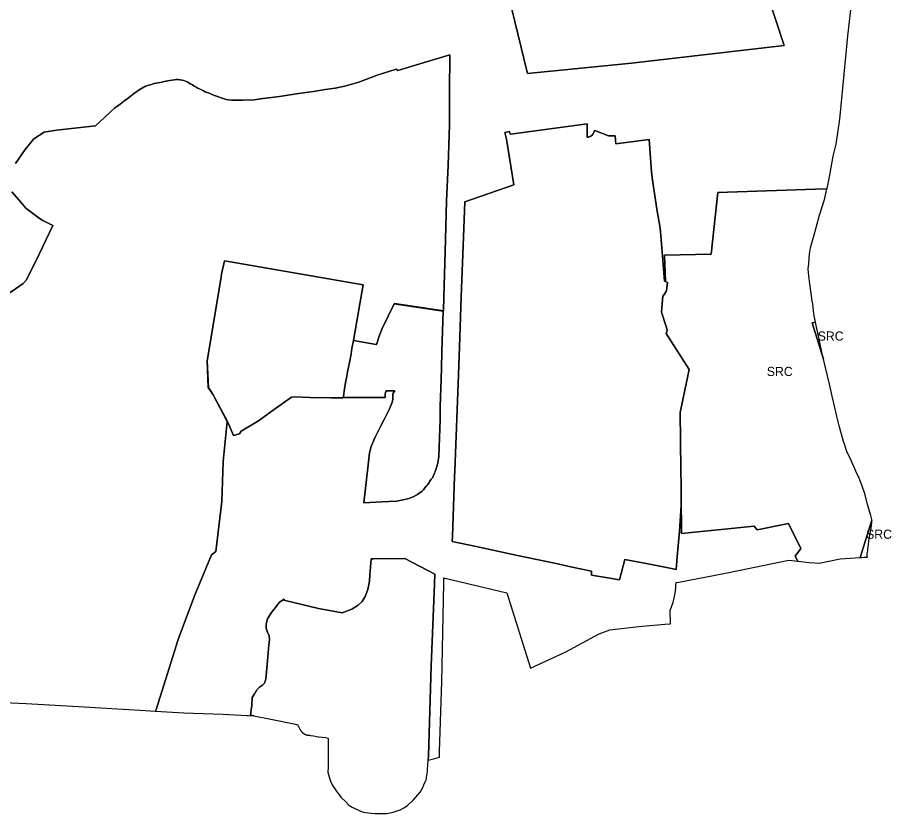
# Model space of a CAD drawing. Extents: x 598968 to 613553, y 4409678 to 4430833.
# Drawn here: x 607096 to 608241, y 4413163 to 4414204 of the extents above; entities that cross this region are included whole.
import ezdxf

# ---------------------------------------------------------------- set-up
doc = ezdxf.new("R2010")
doc.units = 0
doc.layers.add('1', color=7, linetype='Continuous')
doc.layers.add('Sòl Rústic Comú', color=7, linetype='Continuous')

msp = doc.modelspace()

# ---------------------------------------------------------------- linework, layer by layer
at = {"layer": '1'}
for points in [[(607059.8727, 4413308.8178), (607107.6471, 4413306.5122), (607183.5221, 4413302.2202), (607256.6181, 4413297.7362), (607277.0313, 4413296.5408), (607278.5991, 4413300.0182), (607306.7001, 4413390.3762), (607327.9731, 4413447.4722), (607350.3331, 4413501.2922), (607355.9431, 4413505.3322), (607364.0011, 4413570.9642), (607365.7331, 4413623.1222), (607371.1031, 4413675.4722), (607352.3731, 4413710.4522), (607346.1791, 4413719.9522), (607344.5851, 4413755.1552), (607362.9099, 4413864.6394), (607362.9925, 4413864.8818), (607363.5661, 4413868.3492), (607367.4739, 4413886.114), (607370.0765, 4413885.6594), (607548.8117, 4413854.4294), (607544.6407, 4413829.8392), (607536.4941, 4413781.8122), (607536.4871, 4413781.7696), (607566.2069, 4413776.5062), (607566.5121, 4413776.4522), (607570.0921, 4413787.4922), (607573.9321, 4413797.2422), (607589.7593, 4413829.7926), (607589.8321, 4413829.9422), (607654.0611, 4413820.3402), (607654.6501, 4413838.6702), (607655.4701, 4413867.8602), (607656.9201, 4413913.8502), (607658.2501, 4413964.4802), (607660.3901, 4414010.8502), (607661.9101, 4414064.1002), (607661.9201, 4414107.0402), (607662.5601, 4414155.3502), (607623.2501, 4414143.6702), (607594.3101, 4414135.0602), (607592.1921, 4414136.9062), (607567.3801, 4414128.7802), (607543.5301, 4414119.8902), (607524.9801, 4414114.6802), (607512.3901, 4414112.0802), (607499.0601, 4414110.0502), (607483.7601, 4414107.4202), (607464.3601, 4414104.7202), (607439.2501, 4414101.1102), (607414.4501, 4414098.1202), (607406.5221, 4414096.8142), (607391.0301, 4414096.0802), (607376.9201, 4414096.3902), (607372.7101, 4414096.7302), (607369.8101, 4414097.2102), (607367.1801, 4414097.8902), (607364.4601, 4414098.7002), (607361.9701, 4414099.5202), (607359.5601, 4414100.4402), (607357.0501, 4414101.3802), (607354.4501, 4414102.4302), (607352.0601, 4414103.3702), (607349.6301, 4414104.2902), (607347.1901, 4414105.1902), (607344.6301, 4414106.2502), (607342.2101, 4414107.2702), (607339.8001, 4414108.4002), (607337.1901, 4414109.6402), (607334.8501, 4414110.8202), (607332.5901, 4414112.0102), (607330.1501, 4414113.2902), (607327.7301, 4414114.6202), (607325.3101, 4414116.1502), (607323.0601, 4414117.5202), (607320.7701, 4414118.8102), (607318.4701, 4414120.0702), (607316.2601, 4414121.1702), (607314.1001, 4414121.9302), (607311.6901, 4414122.4002), (607309.1601, 4414122.7102), (607306.6401, 4414123.0402), (607304.1701, 4414123.1202), (607301.7701, 4414122.9402), (607298.4301, 4414122.4202), (607295.8701, 4414122.0502), (607293.3601, 4414121.5102), (607290.8901, 4414120.9702), (607288.4201, 4414120.4802), (607285.7801, 4414119.9302), (607283.1301, 4414119.3702), (607280.6201, 4414118.8602), (607277.9001, 4414118.3602), (607275.3801, 4414117.8502), (607272.8601, 4414117.1602), (607270.4701, 4414116.4802), (607268.0201, 4414115.7402), (607265.6601, 4414114.8502), (607263.3001, 4414113.9002), (607261.0901, 4414112.7502), (607258.8301, 4414111.4402), (607256.5801, 4414110.1302), (607254.3101, 4414108.7202), (607252.1601, 4414107.2002), (607249.9701, 4414105.6002), (607247.9201, 4414104.0802), (607245.8101, 4414102.5102), (607243.6901, 4414100.9302), (607241.5701, 4414099.3302), (607239.5001, 4414097.7102), (607237.5001, 4414096.1802), (607235.3601, 4414094.5102), (607233.1801, 4414092.8102), (607230.9701, 4414091.1202), (607228.8901, 4414089.6402), (607226.8301, 4414088.1502), (607224.6501, 4414086.5202), (607223.5151, 4414085.6702), (607198.6701, 4414062.6802), (607147.2901, 4414057.1402), (607131.4201, 4414054.4502), (607117.6701, 4414045.7102), (607106.3501, 4414031.4602), (607093.9701, 4414013.2802)], [(607088.8511, 4413976.3422), (607100.6371, 4413962.8722), (607107.5101, 4413954.7102), (607124.7601, 4413941.6502), (607129.3801, 4413938.5202), (607142.7501, 4413932.2702), (607125.3101, 4413895.4602), (607108.0401, 4413860.9002), (607103.7301, 4413856.0902), (607056.4101, 4413823.3602)]]:
    msp.add_lwpolyline(points, dxfattribs=at)
for points in [[(607944.9089, 4413858.7852), (607943.7417, 4413859.2762), (607942.8583, 4413870.0186), (607939.2597, 4413913.7774), (607937.7005, 4413928.5378), (607934.1381, 4413950.961), (607927.8055, 4413991.3914), (607926.4053, 4414002.5514), (607923.4817, 4414044.9272), (607879.9537, 4414038.9102), (607878.7987, 4414049.6522), (607870.2405, 4414049.4102), (607852.4447, 4414056.2942), (607849.2007, 4414050.6402), (607847.2997, 4414048.9452), (607843.8507, 4414047.8202), (607842.4807, 4414047.7802), (607842.4867, 4414065.0462), (607745.4465, 4414052.2228), (607741.3737, 4414051.6682), (607740.4897, 4414055.2732), (607734.3227, 4414053.7982), (607736.6207, 4414045.0102), (607746.4247, 4413985.198), (607682.0207, 4413962.9402), (607679.8981, 4413905.6214), (607677.4293, 4413838.9502), (607675.4653, 4413785.9084), (607673.6509, 4413736.9128), (607668.9897, 4413611.0292), (607668.7157, 4413603.6314), (607665.8241, 4413525.5432), (607665.5681, 4413518.6306), (607697.0881, 4413511.914), (607750.9713, 4413500.4324), (607801.5397, 4413489.657), (607822.8529, 4413485.1156), (607847.8637, 4413479.7862), (607847.8207, 4413474.6102), (607872.1025, 4413470.4452), (607884.6377, 4413468.2952), (607891.6977, 4413494.8942), (607926.4711, 4413488.323), (607952.8443, 4413483.3392), (607958.7321, 4413481.7274), (607960.2995, 4413498.361), (607963.3781, 4413532.1988), (607965.2981, 4413565.8708), (607965.4153, 4413577.5268), (607965.5483, 4413590.7882), (607964.9893, 4413612.7812), (607964.0887, 4413687.322), (607975.6747, 4413743.8722), (607945.8757, 4413790.6432), (607946.6063, 4413792.778), (607946.9567, 4413795.8152), (607945.6061, 4413800.1254), (607939.8457, 4413818.5102), (607940.1777, 4413823.6864), (607940.5887, 4413830.0936), (607941.1957, 4413839.5552), (607942.9659, 4413841.9372), (607946.3167, 4413846.4462), (607947.3207, 4413857.7702)], [(607536.4871, 4413781.7696), (607536.4941, 4413781.8122), (607544.6407, 4413829.8392), (607548.8117, 4413854.4294), (607370.0765, 4413885.6594), (607367.4739, 4413886.114), (607363.5661, 4413868.3492), (607362.9925, 4413864.8818), (607344.8441, 4413755.1532), (607346.4381, 4413719.9502), (607352.6321, 4413710.4502), (607371.3621, 4413675.4702), (607379.2821, 4413657.3602), (607383.6021, 4413658.4402), (607386.9621, 4413659.2902), (607389.1921, 4413662.8602), (607411.9771, 4413676.6952), (607431.0821, 4413690.3202), (607455.0521, 4413707.3902), (607459.0321, 4413707.8502), (607479.3821, 4413707.2032), (607506.4421, 4413706.7702), (607522.5021, 4413706.7502), (607523.1377, 4413706.9116), (607523.2845, 4413708.7652), (607524.5545, 4413718.3552), (607525.9715, 4413726.5412), (607527.4885, 4413735.0092), (607528.9335, 4413742.7592), (607529.6945, 4413746.8252), (607530.9265, 4413752.8672), (607533.2145, 4413764.1252), (607534.3355, 4413771.0242), (607536.1345, 4413781.7052), (607536.4665, 4413781.6458)], [(607523.1377, 4413706.9116), (607523.1365, 4413706.8952), (607577.8025, 4413706.8952), (607577.8925, 4413707.9252), (607577.8925, 4413710.9132), (607578.1725, 4413713.4092), (607578.9635, 4413715.9652), (607590.2745, 4413715.9652), (607588.4845, 4413712.9052), (607588.0045, 4413711.3552), (607587.8925, 4413710.3542), (607587.8645, 4413707.0452), (607587.6505, 4413704.8622), (607587.2645, 4413702.4552), (607586.4345, 4413699.8252), (607583.6745, 4413692.3352), (607581.0645, 4413686.8152), (607576.5895, 4413678.3222), (607572.2645, 4413669.9912), (607564.1245, 4413654.1352), (607559.6845, 4413642.7952), (607557.3645, 4413634.7952), (607555.1845, 4413614.9352), (607549.7945, 4413569.3052), (607565.6745, 4413570.1462), (607573.8805, 4413570.5742), (607582.4805, 4413571.0052), (607592.8365, 4413571.5142), (607601.3587, 4413573.1002), (607608.9699, 4413574.9738), (607614.3563, 4413577.1986), (607619.9769, 4413580.126), (607623.6069, 4413582.585), (607625.7147, 4413584.2244), (607628.0565, 4413586.3322), (607629.9301, 4413588.7912), (607632.0379, 4413591.2502), (607633.3259, 4413592.8894), (607635.1995, 4413595.6998), (607636.4875, 4413597.5734), (607638.0097, 4413600.2666), (607640.1259, 4413602.4914), (607641.1797, 4413604.8332), (607642.1165, 4413607.2922), (607643.0533, 4413609.6342), (607643.8729, 4413611.3906), (607644.5755, 4413613.6154), (607645.3951, 4413616.8942), (607646.5661, 4413621.2266), (607648.1345, 4413629.7252), (607648.9845, 4413654.3252), (607649.7145, 4413677.6252), (607650.0045, 4413695.4052), (607650.9345, 4413731.0152), (607651.6445, 4413745.3252), (607652.0045, 4413767.2052), (607652.7845, 4413793.6782), (607653.7035, 4413820.2332), (607589.7593, 4413829.7926), (607573.9321, 4413797.2422), (607570.0921, 4413787.4922), (607566.5121, 4413776.4522), (607566.2069, 4413776.5062), (607536.4871, 4413781.7696), (607536.4665, 4413781.6458), (607536.1345, 4413781.7052), (607534.3355, 4413771.0242), (607533.2145, 4413764.1252), (607530.9265, 4413752.8672), (607529.6945, 4413746.8252), (607528.9335, 4413742.7592), (607527.4885, 4413735.0092), (607525.9715, 4413726.5412), (607524.5545, 4413718.3552), (607523.2845, 4413708.7652)], [(607634.0399, 4413232.2802), (607634.3621, 4413238.1922), (607638.2361, 4413355.6722), (607642.4475, 4413462.6008), (607642.9631, 4413475.6892), (607642.8347, 4413475.7568), (607603.7621, 4413496.3222), (607562.5321, 4413495.7722), (607559.5771, 4413495.7322), (607557.8241, 4413475.0462), (607557.1421, 4413466.7322), (607555.3021, 4413455.5422), (607551.6121, 4413446.3922), (607547.5521, 4413440.2522), (607542.3921, 4413435.3222), (607533.9721, 4413430.1322), (607521.6621, 4413425.3422), (607490.7121, 4413430.9022), (607445.2321, 4413441.7722), (607445.5521, 4413443.1422), (607439.2721, 4413439.0122), (607435.4551, 4413433.9762), (607430.8461, 4413427.7912), (607429.1821, 4413425.7022), (607423.6321, 4413417.1922), (607421.9421, 4413410.9922), (607422.0021, 4413404.9522), (607424.2421, 4413398.4822), (607425.7221, 4413395.5622), (607426.3621, 4413390.0822), (607425.6021, 4413383.2122), (607423.5221, 4413362.3822), (607421.6121, 4413338.4122), (607419.6521, 4413333.3422), (607417.1421, 4413330.4622), (607413.2221, 4413327.9422), (607409.5521, 4413324.2122), (607407.1201, 4413319.7662), (607406.8821, 4413319.3322), (607403.8021, 4413314.2322), (607403.3921, 4413304.0922), (607402.2971, 4413298.2912), (607401.5921, 4413291.2322), (607405.8011, 4413290.4212), (607428.0539, 4413285.9626), (607458.3511, 4413279.8912), (607460.2201, 4413279.3902), (607463.0311, 4413278.6412), (607463.2581, 4413278.4562), (607463.4315, 4413278.2986), (607463.4701, 4413278.2602), (607466.1001, 4413273.0102), (607466.7543, 4413272.2196), (607467.5911, 4413270.5602), (607467.8431, 4413270.2262), (607468.1051, 4413269.8992), (607468.3771, 4413269.5802), (607468.6581, 4413269.2702), (607468.9491, 4413268.9692), (607469.2491, 4413268.6762), (607469.5581, 4413268.3932), (607469.8751, 4413268.1202), (607470.2011, 4413267.8562), (607470.5341, 4413267.6022), (607470.6345, 4413267.5306), (607470.8501, 4413267.2702), (607471.1941, 4413267.1456), (607471.2231, 4413267.1262), (607471.5781, 4413266.9042), (607471.9401, 4413266.6932), (607472.3081, 4413266.4932), (607472.6821, 4413266.3042), (607473.0621, 4413266.1272), (607473.4471, 4413265.9622), (607473.8371, 4413265.8082), (607474.2311, 4413265.6672), (607474.6291, 4413265.5372), (607475.0311, 4413265.4202), (607475.4371, 4413265.3152), (607475.8451, 4413265.2222), (607476.2571, 4413265.1422), (607476.6701, 4413265.0752), (607477.0851, 4413265.0202), (607477.5021, 4413264.9782), (607477.9201, 4413264.9492), (607478.3391, 4413264.9322), (607478.7581, 4413264.9292), (607479.9061, 4413264.7342), (607480.4847, 4413264.6388), (607483.7901, 4413264.0802), (607490.2301, 4413263.0202), (607490.4099, 4413263.0044), (607490.8911, 4413262.9252), (607499.5017, 4413262.1204), (607503.2061, 4413261.341), (607503.2061, 4413261.3362), (607503.2001, 4413261.3302), (607503.3611, 4413241.9612), (607502.9901, 4413223.2102), (607502.9311, 4413216.5912), (607505.5601, 4413207.3402), (607506.8101, 4413203.7802), (607509.3101, 4413198.9002), (607512.0001, 4413194.8402), (607513.4311, 4413192.2812), (607516.1901, 4413188.5302), (607519.6211, 4413184.0312), (607525.8111, 4413178.2212), (607530.3811, 4413173.3512), (607534.5711, 4413170.9112), (607534.6833, 4413170.859), (607542.7559, 4413167.0038), (607542.8211, 4413166.9712), (607547.6911, 4413164.9112), (607551.9411, 4413163.7312), (607559.4411, 4413162.7912), (607564.5701, 4413162.6102), (607572.8801, 4413162.5502), (607580.0711, 4413162.5512), (607588.0711, 4413164.1112), (607592.1901, 4413165.4302), (607597.5713, 4413167.4318), (607602.3801, 4413170.1802), (607607.0715, 4413173.0618), (607615.0021, 4413180.3722), (607623.4421, 4413190.4422), (607627.0621, 4413196.4422), (607628.4321, 4413200.1322), (607630.4321, 4413204.8122), (607631.7421, 4413207.5622), (607631.7501, 4413207.6202), (607632.1201, 4413209.8102), (607633.1635, 4413217.7162), (607633.4121, 4413219.4912), (607633.7661, 4413227.2542)]]:
    msp.add_lwpolyline(points, close=True, dxfattribs=at)
at = {"layer": 'Sòl Rústic Comú'}
for points in [[(608032.4405, 4414373.6956), (608100.4405, 4414167.6954), (607900.2507, 4414144.6952), (607764.0617, 4414131.195), (607734.8119, 4414251.695)], [(607734.8119, 4414251.695), (607764.0617, 4414131.195), (607900.2507, 4414144.6952), (608100.4405, 4414167.6954), (608032.4405, 4414373.6956)], [(607093.9701, 4414013.2802), (607106.3501, 4414031.4602), (607117.6701, 4414045.7102), (607131.4201, 4414054.4502), (607147.2901, 4414057.1402), (607198.6701, 4414062.6802), (607223.5151, 4414085.6702), (607224.6501, 4414086.5202), (607226.8301, 4414088.1502), (607228.8901, 4414089.6402), (607230.9701, 4414091.1202), (607233.1801, 4414092.8102), (607235.3601, 4414094.5102), (607237.5001, 4414096.1802), (607239.5001, 4414097.7102), (607241.5701, 4414099.3302), (607243.6901, 4414100.9302), (607245.8101, 4414102.5102), (607247.9201, 4414104.0802), (607249.9701, 4414105.6002), (607252.1601, 4414107.2002), (607254.3101, 4414108.7202), (607256.5801, 4414110.1302), (607258.8301, 4414111.4402), (607261.0901, 4414112.7502), (607263.3001, 4414113.9002), (607265.6601, 4414114.8502), (607268.0201, 4414115.7402), (607270.4701, 4414116.4802), (607272.8601, 4414117.1602), (607275.3801, 4414117.8502), (607277.9001, 4414118.3602), (607280.6201, 4414118.8602), (607283.1301, 4414119.3702), (607285.7801, 4414119.9302), (607288.4201, 4414120.4802), (607290.8901, 4414120.9702), (607293.3601, 4414121.5102), (607295.8701, 4414122.0502), (607298.4301, 4414122.4202), (607301.7701, 4414122.9402), (607304.1701, 4414123.1202), (607306.6401, 4414123.0402), (607309.1601, 4414122.7102), (607311.6901, 4414122.4002), (607314.1001, 4414121.9302), (607316.2601, 4414121.1702), (607318.4701, 4414120.0702), (607320.7701, 4414118.8102), (607323.0601, 4414117.5202), (607325.3101, 4414116.1502), (607327.7301, 4414114.6202), (607330.1501, 4414113.2902), (607332.5901, 4414112.0102), (607334.8501, 4414110.8202), (607337.1901, 4414109.6402), (607339.8001, 4414108.4002), (607342.2101, 4414107.2702), (607344.6301, 4414106.2502), (607347.1901, 4414105.1902), (607349.6301, 4414104.2902), (607352.0601, 4414103.3702), (607354.4501, 4414102.4302), (607357.0501, 4414101.3802), (607359.5601, 4414100.4402), (607361.9701, 4414099.5202), (607364.4601, 4414098.7002), (607367.1801, 4414097.8902), (607369.8101, 4414097.2102), (607372.7101, 4414096.7302), (607376.9201, 4414096.3902), (607391.0301, 4414096.0802), (607406.5221, 4414096.8142), (607414.4501, 4414098.1202), (607439.2501, 4414101.1102), (607464.3601, 4414104.7202), (607483.7601, 4414107.4202), (607499.0601, 4414110.0502), (607512.3901, 4414112.0802), (607524.9801, 4414114.6802), (607543.5301, 4414119.8902), (607567.3801, 4414128.7802), (607592.1921, 4414136.9062), (607594.3101, 4414135.0602), (607623.2501, 4414143.6702), (607662.5601, 4414155.3502), (607661.9201, 4414107.0402), (607661.9101, 4414064.1002), (607660.3901, 4414010.8502), (607658.2501, 4413964.4802), (607656.9201, 4413913.8502), (607655.4701, 4413867.8602), (607654.6501, 4413838.6702), (607654.0611, 4413820.3402), (607589.8321, 4413829.9422), (607589.7593, 4413829.7926), (607653.7035, 4413820.2332), (607652.7845, 4413793.6782), (607652.0045, 4413767.2052), (607651.6445, 4413745.3252), (607650.9345, 4413731.0152), (607650.0045, 4413695.4052), (607649.7145, 4413677.6252), (607648.9845, 4413654.3252), (607648.1345, 4413629.7252), (607646.5661, 4413621.2266), (607645.3951, 4413616.8942), (607644.5755, 4413613.6154), (607643.8729, 4413611.3906), (607643.0533, 4413609.6342), (607642.1165, 4413607.2922), (607641.1797, 4413604.8332), (607640.1259, 4413602.4914), (607638.0097, 4413600.2666), (607636.4875, 4413597.5734), (607635.1995, 4413595.6998), (607633.3259, 4413592.8894), (607632.0379, 4413591.2502), (607629.9301, 4413588.7912), (607628.0565, 4413586.3322), (607625.7147, 4413584.2244), (607623.6069, 4413582.585), (607619.9769, 4413580.126), (607614.3563, 4413577.1986), (607608.9699, 4413574.9738), (607601.3587, 4413573.1002), (607592.8365, 4413571.5142), (607582.4805, 4413571.0052), (607573.8805, 4413570.5742), (607565.6745, 4413570.1462), (607549.7945, 4413569.3052), (607555.1845, 4413614.9352), (607557.3645, 4413634.7952), (607559.6845, 4413642.7952), (607564.1245, 4413654.1352), (607572.2645, 4413669.9912), (607576.5895, 4413678.3222), (607581.0645, 4413686.8152), (607583.6745, 4413692.3352), (607586.4345, 4413699.8252), (607587.2645, 4413702.4552), (607587.6505, 4413704.8622), (607587.8645, 4413707.0452), (607587.8925, 4413710.3542), (607588.0045, 4413711.3552), (607588.4845, 4413712.9052), (607590.2745, 4413715.9652), (607578.9635, 4413715.9652), (607578.1725, 4413713.4092), (607577.8925, 4413710.9132), (607577.8925, 4413707.9252), (607577.8025, 4413706.8952), (607523.1365, 4413706.8952), (607523.1377, 4413706.9116), (607522.5021, 4413706.7502), (607506.4421, 4413706.7702), (607479.3821, 4413707.2032), (607459.0321, 4413707.8502), (607455.0521, 4413707.3902), (607431.0821, 4413690.3202), (607411.9771, 4413676.6952), (607389.1921, 4413662.8602), (607386.9621, 4413659.2902), (607383.6021, 4413658.4402), (607379.2821, 4413657.3602), (607371.3621, 4413675.4702), (607352.6321, 4413710.4502), (607346.4381, 4413719.9502), (607344.8441, 4413755.1532), (607362.9925, 4413864.8818), (607362.9099, 4413864.6394), (607344.5851, 4413755.1552), (607346.1791, 4413719.9522), (607352.3731, 4413710.4522), (607371.1031, 4413675.4722), (607365.7331, 4413623.1222), (607364.0011, 4413570.9642), (607355.9431, 4413505.3322), (607350.3331, 4413501.2922), (607327.9731, 4413447.4722), (607306.7001, 4413390.3762), (607278.5991, 4413300.0182), (607277.0313, 4413296.5408), (607314.0301, 4413294.3702), (607365.3001, 4413292.4002), (607396.9301, 4413290.9102), (607398.3201, 4413290.7802), (607405.8011, 4413290.4212), (607401.5921, 4413291.2322), (607402.2971, 4413298.2912), (607403.3921, 4413304.0922), (607403.8021, 4413314.2322), (607406.8821, 4413319.3322), (607407.1201, 4413319.7662), (607409.5521, 4413324.2122), (607413.2221, 4413327.9422), (607417.1421, 4413330.4622), (607419.6521, 4413333.3422), (607421.6121, 4413338.4122), (607423.5221, 4413362.3822), (607425.6021, 4413383.2122), (607426.3621, 4413390.0822), (607425.7221, 4413395.5622), (607424.2421, 4413398.4822), (607422.0021, 4413404.9522), (607421.9421, 4413410.9922), (607423.6321, 4413417.1922), (607429.1821, 4413425.7022), (607430.8461, 4413427.7912), (607435.4551, 4413433.9762), (607439.2721, 4413439.0122), (607445.5521, 4413443.1422), (607445.2321, 4413441.7722), (607490.7121, 4413430.9022), (607521.6621, 4413425.3422), (607533.9721, 4413430.1322), (607542.3921, 4413435.3222), (607547.5521, 4413440.2522), (607551.6121, 4413446.3922), (607555.3021, 4413455.5422), (607557.1421, 4413466.7322), (607557.8241, 4413475.0462), (607559.5771, 4413495.7322), (607562.5321, 4413495.7722), (607603.7621, 4413496.3222), (607642.8347, 4413475.7568), (607642.9631, 4413475.6892), (607642.4475, 4413462.6008), (607638.2361, 4413355.6722), (607634.3621, 4413238.1922), (607634.0399, 4413232.2802), (607642.6491, 4413234.5898), (607645.9065, 4413235.4679), (607648.93, 4413236.2801), (607648.9699, 4413237.5474), (607649.0339, 4413239.5789), (607649.07, 4413240.7259), (607649.0996, 4413241.6666), (607649.1202, 4413242.3213), (607649.1407, 4413242.9709), (607649.1605, 4413243.499), (607652.0401, 4413335.0502), (607654.6401, 4413463.9702), (607654.6361, 4413463.9744), (607654.7701, 4413470.8702), (607656.1451, 4413470.544), (607656.1671, 4413470.5422), (607656.1701, 4413470.5402), (607736.9301, 4413451.3802), (607768.0701, 4413352.7702), (607814.4201, 4413374.3502), (607857.9601, 4413397.5902), (607871.8101, 4413402.8302), (607910.0601, 4413407.4002), (607944.0279, 4413410.2044), (607951.44, 4413410.8001), (607951.1179, 4413428.7092), (607954.74, 4413438.9101), (607957.55, 4413450.8101), (607958.2472, 4413457.4289), (607958.5445, 4413460.2514), (607959.0301, 4413464.8602), (607962.1701, 4413465.2102), (608023.2901, 4413477.3102), (608106.1801, 4413494.3002), (608117.9629, 4413492.8914), (608114.7505, 4413499.1948), (608122.0007, 4413509.195), (608106.0007, 4413542.195), (608064.9377, 4413533.6948), (608060.8751, 4413538.6948), (607965.9991, 4413529.1948), (607965.4153, 4413577.5268), (607965.2981, 4413565.8708), (607963.3781, 4413532.1988), (607960.2995, 4413498.361), (607958.7321, 4413481.7274), (607952.8443, 4413483.3392), (607926.4711, 4413488.323), (607891.6977, 4413494.8942), (607884.6377, 4413468.2952), (607872.1025, 4413470.4452), (607847.8207, 4413474.6102), (607847.8637, 4413479.7862), (607822.8529, 4413485.1156), (607801.5397, 4413489.657), (607750.9713, 4413500.4324), (607697.0881, 4413511.914), (607665.5681, 4413518.6306), (607665.8241, 4413525.5432), (607668.7157, 4413603.6314), (607668.9897, 4413611.0292), (607673.6509, 4413736.9128), (607675.4653, 4413785.9084), (607677.4293, 4413838.9502), (607679.8981, 4413905.6214), (607682.0207, 4413962.9402), (607746.4247, 4413985.198), (607736.6207, 4414045.0102), (607734.3227, 4414053.7982), (607740.4897, 4414055.2732), (607741.3737, 4414051.6682), (607745.4465, 4414052.2228), (607842.4867, 4414065.0462), (607842.4807, 4414047.7802), (607843.8507, 4414047.8202), (607847.2997, 4414048.9452), (607849.2007, 4414050.6402), (607852.4447, 4414056.2942), (607870.2405, 4414049.4102), (607878.7987, 4414049.6522), (607879.9537, 4414038.9102), (607923.4817, 4414044.9272), (607926.4053, 4414002.5514), (607927.8055, 4413991.3914), (607934.1381, 4413950.961), (607937.7005, 4413928.5378), (607939.2597, 4413913.7774), (607942.8583, 4413870.0186), (607943.7417, 4413859.2762), (607944.9089, 4413858.7852), (607943.6877, 4413893.195), (608004.5633, 4413894.6952), (608013.4387, 4413975.1952), (608153.8777, 4413980.1954), (608156.1709, 4413979.779), (608156.3801, 4413980.6402), (608158.1301, 4413989.4802), (608160.3001, 4414000.4502), (608164.5401, 4414022.7002), (608168.3601, 4414038.6702), (608173.0201, 4414071.4702), (608176.0301, 4414102.7402), (608183.5201, 4414180.4702), (608189.2301, 4414229.5302)], [(607056.4101, 4413823.3602), (607103.7301, 4413856.0902), (607108.0401, 4413860.9002), (607125.3101, 4413895.4602), (607142.7501, 4413932.2702), (607129.3801, 4413938.5202), (607124.7601, 4413941.6502), (607107.5101, 4413954.7102), (607100.6371, 4413962.8722), (607088.8511, 4413976.3422)]]:
    msp.add_lwpolyline(points, dxfattribs=at)
for points in [[(608156.1709, 4413979.779), (608153.8777, 4413980.1954), (608013.4387, 4413975.1952), (608004.5633, 4413894.6952), (607943.6877, 4413893.195), (607944.9089, 4413858.7852), (607947.3207, 4413857.7702), (607946.3167, 4413846.4462), (607942.9659, 4413841.9372), (607941.1957, 4413839.5552), (607940.5887, 4413830.0936), (607940.1777, 4413823.6864), (607939.8457, 4413818.5102), (607945.6061, 4413800.1254), (607946.9567, 4413795.8152), (607946.6063, 4413792.778), (607945.8757, 4413790.6432), (607975.6747, 4413743.8722), (607964.0887, 4413687.322), (607964.9893, 4413612.7812), (607965.5483, 4413590.7882), (607965.4153, 4413577.5268), (607965.9991, 4413529.1948), (608060.8751, 4413538.6948), (608064.9377, 4413533.6948), (608106.0007, 4413542.195), (608122.0007, 4413509.195), (608114.7505, 4413499.1948), (608117.9629, 4413492.8914), (608133.5301, 4413491.0302), (608145.9701, 4413490.0402), (608173.6501, 4413496.0402), (608199.8745, 4413497.685), (608215.2155, 4413546.5908), (608215.2401, 4413547.4502), (608213.5401, 4413552.7902), (608209.5701, 4413566.7902), (608206.1701, 4413579.6102), (608201.9701, 4413592.2102), (608198.3401, 4413601.5102), (608194.0301, 4413610.5902), (608187.0301, 4413626.8602), (608182.9401, 4413635.0302), (608178.7401, 4413647.1702), (608178.1401, 4413649.2402), (608175.3401, 4413658.8602), (608172.0501, 4413670.1002), (608169.3101, 4413682.0402), (608169.2101, 4413682.4602), (608163.1001, 4413708.7002), (608159.7001, 4413724.4702), (608154.2501, 4413746.1402), (608151.5323, 4413757.4124), (608136.8145, 4413804.6952), (608141.3719, 4413805.5508), (608139.1701, 4413816.7402), (608137.6001, 4413829.4602), (608137.4701, 4413830.5802), (608133.9501, 4413855.8402), (608132.7001, 4413866.1702), (608131.5701, 4413874.7902), (608132.4801, 4413882.4002), (608133.3801, 4413894.8802), (608134.7501, 4413903.0502), (608136.2101, 4413907.8802), (608140.5701, 4413923.1502), (608146.6701, 4413945.6002), (608152.8601, 4413966.1502)], [(608151.5323, 4413757.4124), (608150.3901, 4413762.1502), (608145.4601, 4413785.7402), (608142.2301, 4413801.1902), (608141.3719, 4413805.5508), (608136.8145, 4413804.6952)], [(608199.8745, 4413497.685), (608201.8689, 4413497.8098), (608205.0732, 4413498.0052), (608209.31, 4413498.2701), (608208.9, 4413500.1901), (608209.1411, 4413502.2968), (608209.4254, 4413504.7798), (608209.6029, 4413506.3311), (608209.7045, 4413507.2188), (608209.7001, 4413507.2202), (608209.8101, 4413508.1402), (608211.6201, 4413521.8702), (608214.1101, 4413535.9902), (608215.1301, 4413543.6002), (608215.2155, 4413546.5908)]]:
    msp.add_lwpolyline(points, close=True, dxfattribs=at)

# ---------------------------------------------------------------- texts
for p in [(608144.1734, 4413781.4816), (608077.5429, 4413735.1178), (608207.545, 4413522.1379)]:
    msp.add_text('SRC', height=12, dxfattribs=at).set_placement(p)

doc.saveas('drawing.dxf')
